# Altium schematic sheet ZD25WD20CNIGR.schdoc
size 127 x 101 mm
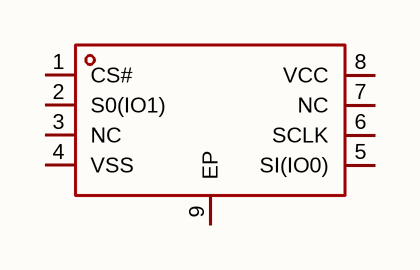
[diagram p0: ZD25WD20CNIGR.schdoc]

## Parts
U?  zd25wd20cnigr  [USON-8_L1.5-W1.5-P0.40-BL-EP]  (value not drawn)

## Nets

Not connected (* = marked no-connect by the designer): U? 1(CS#) 2(S0(IO1)) 3(NC) 4(VSS) 5(SI(IO0)) 6(SCLK) 7(NC) 8(VCC) 9(EP)

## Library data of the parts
U? = zd25wd20cnigr: 接口类型:SPI;存储容量:2Mbit;时钟频率(fc):104MHz;; Manufacturer: Zetta(澜智); AddInBom: yes; ModelId: 5757cbfba7d0405e801eee9fb676df23; ModelName: USON-8_L1.5-W1.5-H0.5-P0.40-BL-EP; ModelTransform: 59.055,59.8424,0,180,0,0,0,0,0; Interface: SPI; Memory Size: 2Mbit; Clock Frequency: 104MHz; Voltage - Supply: 1.65V~3.6V; Standby Supply Current: 0.5uA; Program / Erase Cycles: 100000次; Page Programming Time (Tpp): 2ms; Block Erase Time(tBE): 13ms@(64KB); Data Retention - TDR (Year): 20年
